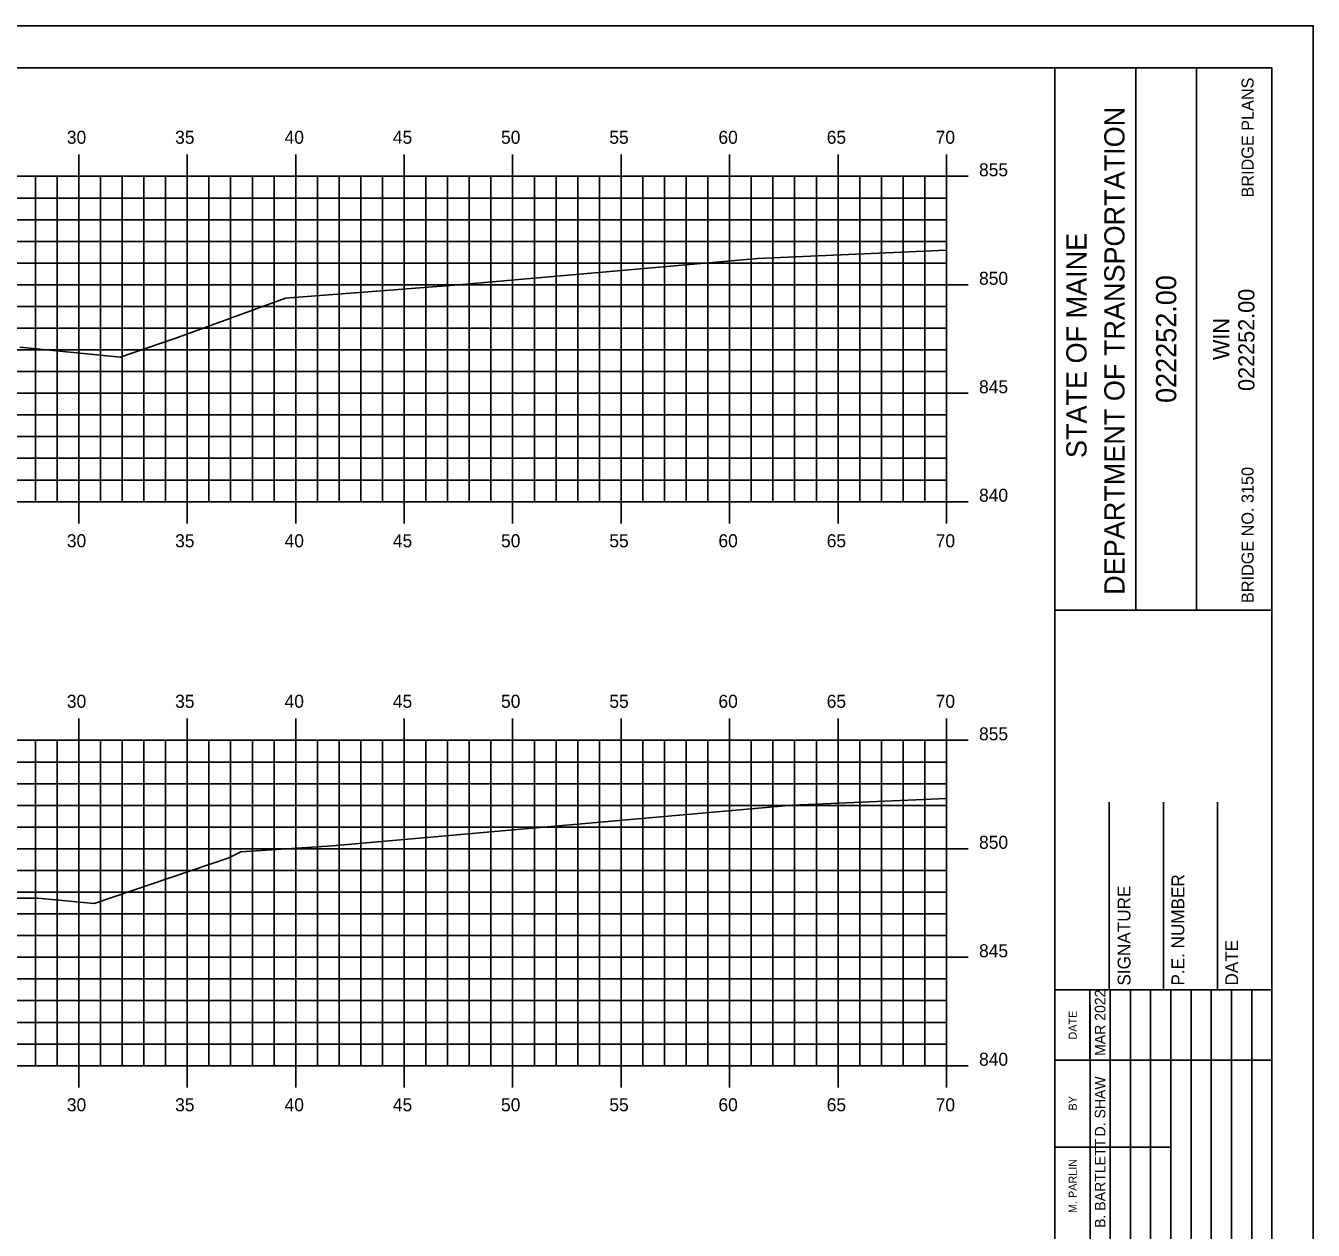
# Model space of a CAD drawing. Extents: x 2194004 to 2194525, y 863888 to 863998.
# Drawn here: x 2194282.5 to 2194341.9, y 863942.9 to 863998.4 of the extents above; entities that cross this region are included whole.
import ezdxf

# ---------------------------------------------------------------- set-up
doc = ezdxf.new("R2010")
doc.units = 0
for name, color, linetype in [('BORDER', 7, 'Continuous'), ('BRIDGE_TITLE', 7, 'Continuous'), ('H_V ANNOTATION', 7, 'Continuous'), ('MAJOR', 7, 'Continuous'), ('MINOR', 7, 'Continuous'), ('PLOT BOUNDARY', 7, 'Continuous'), ('S_Roadway_Centerline', 7, 'Continuous')]:
    doc.layers.add(name, color=color, linetype=linetype)

msp = doc.modelspace()

# ---------------------------------------------------------------- linework, layer by layer
at = {"layer": 'BORDER'}
for p, q in [((2194329.986, 863891.446), (2194329.986, 863996.446)), ((2194333.715, 863971.443), (2194333.715, 863996.443)), ((2194336.51, 863971.443), (2194336.51, 863996.443)), ((2194329.987, 863971.44), (2194339.986, 863971.44)), ((2194332.486, 863953.949), (2194332.486, 863962.596)), ((2194334.986, 863953.949), (2194334.986, 863962.596)), ((2194337.486, 863953.949), (2194337.486, 863962.596)), ((2194329.986, 863953.949), (2194339.986, 863953.949))]:
    msp.add_line(p, q, dxfattribs=at)
msp.add_lwpolyline([(2194179.986, 863891.446), (2194339.986, 863891.446), (2194339.986, 863996.446), (2194179.986, 863996.446)], close=True, dxfattribs=at)
for points in [[(2194331.601, 863950.699), (2194331.601, 863953.949)], [(2194332.534, 863936.452), (2194332.534, 863953.949)], [(2194333.466, 863953.949), (2194333.466, 863936.452)], [(2194334.397, 863936.452), (2194334.397, 863953.949)], [(2194335.329, 863936.452), (2194335.329, 863953.949)], [(2194336.261, 863936.452), (2194336.261, 863953.949)], [(2194337.192, 863936.452), (2194337.192, 863953.949)], [(2194338.124, 863936.452), (2194338.124, 863953.949)], [(2194339.056, 863936.452), (2194339.056, 863953.949)], [(2194331.602, 863936.452), (2194331.602, 863953.243)], [(2194329.986, 863950.699), (2194339.986, 863950.699)], [(2194329.986, 863946.699), (2194331.602, 863946.699)], [(2194331.601, 863946.699), (2194335.328, 863946.699)]]:
    msp.add_lwpolyline(points, dxfattribs=at)
at = {"layer": 'MAJOR'}
for p, q in [((2194284.986, 863992.448), (2194284.986, 863991.446)), ((2194289.986, 863992.448), (2194289.986, 863991.446)), ((2194294.986, 863992.448), (2194294.986, 863991.446)), ((2194299.986, 863992.448), (2194299.986, 863991.446)), ((2194304.986, 863992.448), (2194304.986, 863991.446)), ((2194309.986, 863992.448), (2194309.986, 863991.446)), ((2194314.986, 863992.448), (2194314.986, 863991.446)), ((2194319.986, 863992.448), (2194319.986, 863991.446)), ((2194324.986, 863992.448), (2194324.986, 863991.446)), ((2194184.986, 863991.446), (2194324.986, 863991.446)), ((2194284.986, 863976.446), (2194284.986, 863991.446)), ((2194289.986, 863976.446), (2194289.986, 863991.446)), ((2194294.986, 863976.446), (2194294.986, 863991.446)), ((2194299.986, 863976.446), (2194299.986, 863991.446)), ((2194304.986, 863976.446), (2194304.986, 863991.446)), ((2194309.986, 863976.446), (2194309.986, 863991.446)), ((2194314.986, 863976.446), (2194314.986, 863991.446)), ((2194319.986, 863976.446), (2194319.986, 863991.446)), ((2194325.988, 863991.446), (2194323.984, 863991.446)), ((2194324.986, 863976.446), (2194324.986, 863991.446)), ((2194324.986, 863976.446), (2194324.986, 863991.446)), ((2194184.986, 863986.446), (2194324.986, 863986.446)), ((2194325.988, 863986.446), (2194323.984, 863986.446)), ((2194184.986, 863981.446), (2194324.986, 863981.446)), ((2194325.988, 863981.446), (2194323.984, 863981.446)), ((2194184.986, 863976.446), (2194324.986, 863976.446)), ((2194284.986, 863975.444), (2194284.986, 863976.446)), ((2194289.986, 863975.444), (2194289.986, 863976.446)), ((2194294.986, 863975.444), (2194294.986, 863976.446)), ((2194299.986, 863975.444), (2194299.986, 863976.446)), ((2194304.986, 863975.444), (2194304.986, 863976.446)), ((2194309.986, 863975.444), (2194309.986, 863976.446)), ((2194314.986, 863975.444), (2194314.986, 863976.446)), ((2194319.986, 863975.444), (2194319.986, 863976.446)), ((2194325.988, 863976.446), (2194323.984, 863976.446)), ((2194324.986, 863975.444), (2194324.986, 863976.446)), ((2194284.986, 863966.448), (2194284.986, 863965.446)), ((2194289.986, 863966.448), (2194289.986, 863965.446)), ((2194294.986, 863966.448), (2194294.986, 863965.446)), ((2194299.986, 863966.448), (2194299.986, 863965.446)), ((2194304.986, 863966.448), (2194304.986, 863965.446)), ((2194309.986, 863966.448), (2194309.986, 863965.446)), ((2194314.986, 863966.448), (2194314.986, 863965.446)), ((2194319.986, 863966.448), (2194319.986, 863965.446)), ((2194324.986, 863966.448), (2194324.986, 863965.446)), ((2194184.986, 863965.446), (2194324.986, 863965.446)), ((2194284.986, 863950.446), (2194284.986, 863965.446)), ((2194289.986, 863950.446), (2194289.986, 863965.446)), ((2194294.986, 863950.446), (2194294.986, 863965.446)), ((2194299.986, 863950.446), (2194299.986, 863965.446)), ((2194304.986, 863950.446), (2194304.986, 863965.446)), ((2194309.986, 863950.446), (2194309.986, 863965.446)), ((2194314.986, 863950.446), (2194314.986, 863965.446)), ((2194319.986, 863950.446), (2194319.986, 863965.446)), ((2194325.988, 863965.446), (2194323.984, 863965.446)), ((2194324.986, 863950.446), (2194324.986, 863965.446)), ((2194324.986, 863950.446), (2194324.986, 863965.446)), ((2194184.986, 863960.446), (2194324.986, 863960.446)), ((2194325.988, 863960.446), (2194323.984, 863960.446)), ((2194184.986, 863955.446), (2194324.986, 863955.446)), ((2194325.988, 863955.446), (2194323.984, 863955.446)), ((2194184.986, 863950.446), (2194324.986, 863950.446)), ((2194284.986, 863949.444), (2194284.986, 863950.446)), ((2194289.986, 863949.444), (2194289.986, 863950.446)), ((2194294.986, 863949.444), (2194294.986, 863950.446)), ((2194299.986, 863949.444), (2194299.986, 863950.446)), ((2194304.986, 863949.444), (2194304.986, 863950.446)), ((2194309.986, 863949.444), (2194309.986, 863950.446)), ((2194314.986, 863949.444), (2194314.986, 863950.446)), ((2194319.986, 863949.444), (2194319.986, 863950.446)), ((2194325.988, 863950.446), (2194323.984, 863950.446)), ((2194324.986, 863949.444), (2194324.986, 863950.446))]:
    msp.add_line(p, q, dxfattribs=at)
at = {"layer": 'MINOR'}
for p, q in [((2194282.986, 863976.446), (2194282.986, 863991.446)), ((2194283.986, 863976.446), (2194283.986, 863991.446)), ((2194285.986, 863976.446), (2194285.986, 863991.446)), ((2194286.986, 863976.446), (2194286.986, 863991.446)), ((2194287.986, 863976.446), (2194287.986, 863991.446)), ((2194288.986, 863976.446), (2194288.986, 863991.446)), ((2194290.986, 863976.446), (2194290.986, 863991.446)), ((2194291.986, 863976.446), (2194291.986, 863991.446)), ((2194292.986, 863976.446), (2194292.986, 863991.446)), ((2194293.986, 863976.446), (2194293.986, 863991.446)), ((2194295.986, 863976.446), (2194295.986, 863991.446)), ((2194296.986, 863976.446), (2194296.986, 863991.446)), ((2194297.986, 863976.446), (2194297.986, 863991.446)), ((2194298.986, 863976.446), (2194298.986, 863991.446)), ((2194300.986, 863976.446), (2194300.986, 863991.446)), ((2194301.986, 863976.446), (2194301.986, 863991.446)), ((2194302.986, 863976.446), (2194302.986, 863991.446)), ((2194303.986, 863976.446), (2194303.986, 863991.446)), ((2194305.986, 863976.446), (2194305.986, 863991.446)), ((2194306.986, 863976.446), (2194306.986, 863991.446)), ((2194307.986, 863976.446), (2194307.986, 863991.446)), ((2194308.986, 863976.446), (2194308.986, 863991.446)), ((2194310.986, 863976.446), (2194310.986, 863991.446)), ((2194311.986, 863976.446), (2194311.986, 863991.446)), ((2194312.986, 863976.446), (2194312.986, 863991.446)), ((2194313.986, 863976.446), (2194313.986, 863991.446)), ((2194315.986, 863976.446), (2194315.986, 863991.446)), ((2194316.986, 863976.446), (2194316.986, 863991.446)), ((2194317.986, 863976.446), (2194317.986, 863991.446)), ((2194318.986, 863976.446), (2194318.986, 863991.446)), ((2194320.986, 863976.446), (2194320.986, 863991.446)), ((2194321.986, 863976.446), (2194321.986, 863991.446)), ((2194322.986, 863976.446), (2194322.986, 863991.446)), ((2194323.986, 863976.446), (2194323.986, 863991.446)), ((2194184.986, 863990.446), (2194324.986, 863990.446)), ((2194324.986, 863990.446), (2194323.984, 863990.446)), ((2194184.986, 863989.446), (2194324.986, 863989.446)), ((2194324.986, 863989.446), (2194323.984, 863989.446)), ((2194184.986, 863988.446), (2194324.986, 863988.446)), ((2194324.986, 863988.446), (2194323.984, 863988.446)), ((2194184.986, 863987.446), (2194324.986, 863987.446)), ((2194324.986, 863987.446), (2194323.984, 863987.446)), ((2194184.986, 863985.446), (2194324.986, 863985.446)), ((2194324.986, 863985.446), (2194323.984, 863985.446)), ((2194184.986, 863984.446), (2194324.986, 863984.446)), ((2194324.986, 863984.446), (2194323.984, 863984.446)), ((2194184.986, 863983.446), (2194324.986, 863983.446)), ((2194324.986, 863983.446), (2194323.984, 863983.446)), ((2194184.986, 863982.446), (2194324.986, 863982.446)), ((2194324.986, 863982.446), (2194323.984, 863982.446)), ((2194184.986, 863980.446), (2194324.986, 863980.446)), ((2194324.986, 863980.446), (2194323.984, 863980.446)), ((2194184.986, 863979.446), (2194324.986, 863979.446)), ((2194324.986, 863979.446), (2194323.984, 863979.446)), ((2194184.986, 863978.446), (2194324.986, 863978.446)), ((2194324.986, 863978.446), (2194323.984, 863978.446)), ((2194184.986, 863977.446), (2194324.986, 863977.446)), ((2194324.986, 863977.446), (2194323.984, 863977.446)), ((2194282.986, 863950.446), (2194282.986, 863965.446)), ((2194283.986, 863950.446), (2194283.986, 863965.446)), ((2194285.986, 863950.446), (2194285.986, 863965.446)), ((2194286.986, 863950.446), (2194286.986, 863965.446)), ((2194287.986, 863950.446), (2194287.986, 863965.446)), ((2194288.986, 863950.446), (2194288.986, 863965.446)), ((2194290.986, 863950.446), (2194290.986, 863965.446)), ((2194291.986, 863950.446), (2194291.986, 863965.446)), ((2194292.986, 863950.446), (2194292.986, 863965.446)), ((2194293.986, 863950.446), (2194293.986, 863965.446)), ((2194295.986, 863950.446), (2194295.986, 863965.446)), ((2194296.986, 863950.446), (2194296.986, 863965.446)), ((2194297.986, 863950.446), (2194297.986, 863965.446)), ((2194298.986, 863950.446), (2194298.986, 863965.446)), ((2194300.986, 863950.446), (2194300.986, 863965.446)), ((2194301.986, 863950.446), (2194301.986, 863965.446)), ((2194302.986, 863950.446), (2194302.986, 863965.446)), ((2194303.986, 863950.446), (2194303.986, 863965.446)), ((2194305.986, 863950.446), (2194305.986, 863965.446)), ((2194306.986, 863950.446), (2194306.986, 863965.446)), ((2194307.986, 863950.446), (2194307.986, 863965.446)), ((2194308.986, 863950.446), (2194308.986, 863965.446)), ((2194310.986, 863950.446), (2194310.986, 863965.446)), ((2194311.986, 863950.446), (2194311.986, 863965.446)), ((2194312.986, 863950.446), (2194312.986, 863965.446)), ((2194313.986, 863950.446), (2194313.986, 863965.446)), ((2194315.986, 863950.446), (2194315.986, 863965.446)), ((2194316.986, 863950.446), (2194316.986, 863965.446)), ((2194317.986, 863950.446), (2194317.986, 863965.446)), ((2194318.986, 863950.446), (2194318.986, 863965.446)), ((2194320.986, 863950.446), (2194320.986, 863965.446)), ((2194321.986, 863950.446), (2194321.986, 863965.446)), ((2194322.986, 863950.446), (2194322.986, 863965.446)), ((2194323.986, 863950.446), (2194323.986, 863965.446)), ((2194184.986, 863964.446), (2194324.986, 863964.446)), ((2194324.986, 863964.446), (2194323.984, 863964.446)), ((2194184.986, 863963.446), (2194324.986, 863963.446)), ((2194324.986, 863963.446), (2194323.984, 863963.446)), ((2194184.986, 863962.446), (2194324.986, 863962.446)), ((2194324.986, 863962.446), (2194323.984, 863962.446)), ((2194184.986, 863961.446), (2194324.986, 863961.446)), ((2194324.986, 863961.446), (2194323.984, 863961.446)), ((2194184.986, 863959.446), (2194324.986, 863959.446)), ((2194324.986, 863959.446), (2194323.984, 863959.446)), ((2194184.986, 863958.446), (2194324.986, 863958.446)), ((2194324.986, 863958.446), (2194323.984, 863958.446)), ((2194184.986, 863957.446), (2194324.986, 863957.446)), ((2194324.986, 863957.446), (2194323.984, 863957.446)), ((2194184.986, 863956.446), (2194324.986, 863956.446)), ((2194324.986, 863956.446), (2194323.984, 863956.446)), ((2194184.986, 863954.446), (2194324.986, 863954.446)), ((2194324.986, 863954.446), (2194323.984, 863954.446)), ((2194184.986, 863953.446), (2194324.986, 863953.446)), ((2194324.986, 863953.446), (2194323.984, 863953.446)), ((2194184.986, 863952.446), (2194324.986, 863952.446)), ((2194324.986, 863952.446), (2194323.984, 863952.446)), ((2194184.986, 863951.446), (2194324.986, 863951.446)), ((2194324.986, 863951.446), (2194323.984, 863951.446))]:
    msp.add_line(p, q, dxfattribs=at)
at = {"layer": 'PLOT BOUNDARY'}
msp.add_lwpolyline([(2194171.893, 863888.387), (2194341.893, 863888.387), (2194341.893, 863998.387), (2194171.893, 863998.387)], close=True, dxfattribs=at)
at = {"layer": 'S_Roadway_Centerline'}
for points in [[(2194282.269, 863983.567), (2194286.889, 863983.115), (2194289.458, 863983.987), (2194294.515, 863985.827), (2194302.301, 863986.421), (2194316.283, 863987.66), (2194324.986, 863988.035)], [(2194281.743, 863958.166), (2194283.095, 863958.173), (2194285.692, 863957.918), (2194291.904, 863960.026), (2194292.449, 863960.3), (2194296.681, 863960.577), (2194317.881, 863962.455), (2194324.986, 863962.762)]]:
    msp.add_lwpolyline(points, dxfattribs=at)

# ---------------------------------------------------------------- texts
at = {"layer": 'BORDER'}
for s, height, p in [('DEPARTMENT OF TRANSPORTATION', 0.93176, (2194333.193, 863972.152)), ('STATE OF MAINE', 0.93176, (2194331.442, 863978.458)), ('022252.00', 0.9318, (2194335.578, 863980.999)), ('022252.00', 0.7453, (2194339.182, 863981.551)), ('WIN', 0.7453, (2194338.023, 863982.976)), ('P.E. NUMBER', 0.59055, (2194335.947, 863954.141)), ('SIGNATURE', 0.5906, (2194333.467, 863954.141)), ('DATE', 0.5906, (2194338.427, 863954.141)), ('MAR 2022', 0.4845, (2194332.309, 863950.897)), ('DATE', 0.3714, (2194330.991, 863951.654)), ('D. SHAW', 0.4845, (2194332.309, 863947.184)), ('BY', 0.3714, (2194330.991, 863948.384)), ('B. BARTLETT', 0.48455, (2194332.309, 863942.972)), ('M. PARLIN', 0.3727, (2194330.991, 863943.656))]:
    msp.add_text(s, height=height, rotation=90, dxfattribs=at).set_placement(p)
at = {"layer": 'BRIDGE_TITLE'}
for s, p in [('BRIDGE PLANS', (2194339.145, 863990.47)), ('BRIDGE NO. 3150', (2194339.145, 863971.776))]:
    msp.add_text(s, height=0.55901, rotation=90, dxfattribs=at).set_placement(p)
at = {"layer": 'H_V ANNOTATION'}
for s, p in [('30', (2194284.435, 863992.946)), ('35', (2194289.427, 863992.946)), ('40', (2194294.472, 863992.946)), ('45', (2194299.464, 863992.946)), ('50', (2194304.451, 863992.946)), ('55', (2194309.443, 863992.946)), ('60', (2194314.472, 863992.946)), ('65', (2194319.464, 863992.946)), ('70', (2194324.488, 863992.946)), ('855', (2194326.486, 863991.446)), ('850', (2194326.486, 863986.446)), ('845', (2194326.486, 863981.446)), ('840', (2194326.486, 863976.446)), ('30', (2194284.435, 863974.346)), ('35', (2194289.427, 863974.346)), ('40', (2194294.472, 863974.346)), ('45', (2194299.464, 863974.346)), ('50', (2194304.451, 863974.346)), ('55', (2194309.443, 863974.346)), ('60', (2194314.472, 863974.346)), ('65', (2194319.464, 863974.346)), ('70', (2194324.488, 863974.346)), ('30', (2194284.435, 863966.946)), ('35', (2194289.427, 863966.946)), ('40', (2194294.472, 863966.946)), ('45', (2194299.464, 863966.946)), ('50', (2194304.451, 863966.946)), ('55', (2194309.443, 863966.946)), ('60', (2194314.472, 863966.946)), ('65', (2194319.464, 863966.946)), ('70', (2194324.488, 863966.946)), ('855', (2194326.486, 863965.446)), ('850', (2194326.486, 863960.446)), ('845', (2194326.486, 863955.446)), ('840', (2194326.486, 863950.446)), ('30', (2194284.435, 863948.346)), ('35', (2194289.427, 863948.346)), ('40', (2194294.472, 863948.346)), ('45', (2194299.464, 863948.346)), ('50', (2194304.451, 863948.346)), ('55', (2194309.443, 863948.346)), ('60', (2194314.472, 863948.346)), ('65', (2194319.464, 863948.346)), ('70', (2194324.488, 863948.346))]:
    msp.add_text(s, height=0.6, dxfattribs=at).set_placement(p)

doc.saveas('drawing.dxf')
